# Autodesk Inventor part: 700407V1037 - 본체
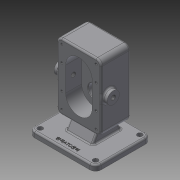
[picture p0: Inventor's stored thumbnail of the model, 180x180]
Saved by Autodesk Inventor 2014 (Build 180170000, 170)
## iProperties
Created: 2020-04
Part Number: 700407V1037 - 본체
Material: Generic
Document SubType Name: Modeling
Designer: kh
Density: 1 g/cm^3
Appearance: Default
Author: kh
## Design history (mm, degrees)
sketch "스케치1"
  geometry: L1 (-50, 60)-(50, 60); L2 (50, 60)-(50, -60); L3 (50, -60)-(-50, -60); L4 (-50, -60)-(-50, 60); L5 (-50, 60)-(50, -60); L6 (50, 60)-(-50, -60); 1 further point
  constraints: 12 end point, 2 midpoint, 2 parallel, 1 horizontal, 1 perpendicular
  dimensions: "d0" = 100 distance of L2.end L3.end; "d1" = 120 distance of L1.end L2.end
extrude "돌출1" new body sketch "스케치1" stored distance "d2" = 10; taper "d3" = 0 deg
node "작업 평면2"
  node "작업 평면1"
sketch "스케치2"
  geometry: L1 (-120, 0)-(-120, -10) reference; L2 (0, 0)-(-120, 0) reference; L3 (0, 0)-(0, -10) reference; L4 (-120, -10)-(0, -10) reference; L5 (-100, 140)-(-20, 140); L6 (-20, 140)-(-20, 20); L7 (-20, 20)-(-100, 20); L8 (-100, 20)-(-100, 140); L9 (-20, 80)-(-100, 80); L10 (-60, 20)-(-60, 80); 1 further point
  constraints: 12 end point, 4 midpoint, 2 parallel, 1 horizontal, 1 perpendicular, 1 point on line
  dimensions: "d5" = 80 distance of L5.start L5.end; "d6" = 150 distance between parallel lines of L5 L4; "d7" = 90 distance between parallel lines of L9 L4
extrude "돌출2" join sketch "스케치2" distance "d8" = 53; taper "d9" = 0 deg
fillet "모깎기1" dims "d10" = 9
sketch "스케치4"
  geometry: L1 (20, 29)-(20, 91) reference; L2 (131, 20)-(29, 20) reference; L3 (140, 91)-(140, 29) reference; L4 (29, 100)-(131, 100) reference; L5 (102, 60)-(58, 60); L6 (102, 84)-(58, 84); L7 (58, 36)-(102, 36); L8 (20, 29)-(20, 91) reference; L9 (80, 100)-(80, 20); C1 r 12.5 at (102, 60); C2 r 12.5 at (58, 60); C3 r 8.5 at (102, 60); C4 r 8.5 at (58, 60); A1 r 9 centre (29, 91) between (29, 100) and (20, 91) reference; A2 r 9 centre (29, 29) between (20, 29) and (29, 20) reference; A3 r 9 centre (131, 29) between (131, 20) and (140, 29) reference; A4 r 9 centre (131, 91) between (140, 91) and (131, 100) reference; A5 r 24 centre (102, 60) between (102, 36) and (102, 84); A6 r 24 centre (58, 60) between (58, 84) and (58, 36); 3 further points
  constraints: 10 end point, 6 centre point, 5 coincident, 4 midpoint, 4 point on circle, 4 tangent, 1 parallel, 1 perpendicular
  dimensions: "d11" = 44 distance of L5.end L5.start; "d12" = 24 radius of A5; "d13" = 25 diameter of C1; "d14" = 25 diameter of C2; "d15" = 17 diameter of C3; "d16" = 17 diameter of C4
  node "투영된 루프5"
extrude "돌출3" cut sketch "스케치4" distance "d17" = 29; taper "d18" = 0 deg
extrude "돌출4" cut sketch "스케치4" distance "d19" = 44; taper "d20" = 0 deg
extrude "돌출5" cut sketch "스케치4" distance "d21" = 44; taper "d22" = 0 deg
sketch "스케치5"
  geometry: L1 (-29, 100)-(-131, 100) reference; L2 (-140, 91)-(-140, 29) reference; L3 (-131, 20)-(-29, 20) reference; L4 (-20, 29)-(-20, 91) reference; C1 r 8.5 at (-102, 60) reference; C2 r 14 at (-102, 60); C3 r 8.5 at (-102, 60); A1 r 9 centre (-29, 91) between (-20, 91) and (-29, 100) reference; A2 r 9 centre (-131, 91) between (-131, 100) and (-140, 91) reference; A3 r 9 centre (-131, 29) between (-140, 29) and (-131, 20) reference; A4 r 9 centre (-29, 29) between (-29, 20) and (-20, 29) reference; 1 further point
  constraints: 2 centre point, 2 coincident
  dimensions: "d23" = 28 diameter of C2; "d24" = 17 diameter of C3
  node "투영된 루프6"
extrude "돌출7" cut sketch "스케치5" stored distance "d27" = 7.3; taper "d28" = 0 deg
node "작업 평면5"
  node "작업 평면4"
sketch "스케치6"
  geometry: C1 r 12.5 at (38, 0) reference; C2 r 19 at (38, 0); C3 r 14 at (38, 0); 1 further point
  constraints: 2 centre point, 2 coincident
  dimensions: "d30" = 38 diameter of C2; "d31" = 28 diameter of C3
extrude "돌출8" join sketch "스케치6" distance "d32" = 17; taper "d33" = 0 deg
extrude "돌출9" cut sketch "스케치4" stored distance "d34" = 7.3; taper "d35" = 0 deg
node "작업 평면7"
  node "작업 평면6"
sketch "스케치9"
  geometry: L1 (53, -102)-(0, -102) reference; L2 (53, 0)-(53, -102) reference; L3 (0, 0)-(53, 0) reference; L4 (0, 0)-(0, -102) reference; L5 (70, -141)-(-30, -141) reference; C1 r 11 at (14, -51); 1 further point
  constraints: 1 centre point
  dimensions: "d37" = 22 diameter of C1; "d38" = 90 distance from line of C1.centre L5; "d39" = 14 distance from line of L4 C1.centre
extrude "돌출10" join sketch "스케치9" stored distance "d40" = 7.3; taper "d41" = 0 deg
node "작업 평면8"
sketch "스케치10"
  geometry: L1 (44, 16.5)-(44, 41.5) reference; L2 (0, 102)-(53, 102) reference; L3 (0, 102)-(0, 0) reference; L4 (53, 0)-(0, 0) reference; L5 (53, 102)-(53, 0) reference; L6 (-30, 141)-(70, 141) reference; C1 r 11 at (14, 51); 1 further point
  constraints: 1 centre point
  dimensions: "d43" = 22 diameter of C1; "d44" = 90 distance from line of C1.centre L6; "d45" = 14 distance from line of L3 C1.centre
extrude "돌출11" join sketch "스케치10" stored distance "d46" = 7.3; taper "d47" = 0 deg
sketch "스케치11"
  geometry: C1 r 11 at (0, 0) reference; 2 further points
  constraints: 1 coincident
hole "구멍1" sketch "스케치11" at (0, 0) diameter "d48" = 8.376; stored, may be unused: countersink angle "d52" = 90 deg, drill point angle "d54" = 118 deg; dims "d49" = 6, "d50" = 4, "d51" = 2, "d53" = 8
sketch "스케치12"
  geometry: L1 (58, 84)-(102, 84) reference; L2 (102, 36)-(58, 36) reference; L3 (20, 29)-(20, 91) reference; L4 (131, 20)-(29, 20) reference; L5 (140, 91)-(140, 29) reference; L6 (29, 100)-(131, 100) reference; L7 (126, 60)-(34, 60); L8 (80, 84)-(80, 36); A1 r 24 centre (58, 60) between (58, 84) and (58, 36) reference; A2 r 24 centre (102, 60) between (102, 36) and (102, 84) reference; A3 r 9 centre (29, 91) between (29, 100) and (20, 91) reference; A4 r 9 centre (29, 29) between (20, 29) and (29, 20) reference; A5 r 9 centre (131, 29) between (131, 20) and (140, 29) reference; A6 r 9 centre (131, 91) between (140, 91) and (131, 100) reference; 9 further points
  constraints: 4 coincident, 4 end point, 2 midpoint, 2 point on circle, 2 symmetric about line
  dimensions: "d57" = 29 distance of point (29, 29) point (58, 29); "d58" = 29 distance of point (58, 91) point (29, 91); "d60" = 62 distance of point (58, 29) point (58, 91); "d64" = 44 distance of point (58, 29) point (102, 29)
hole "구멍2" sketch "스케치12" at (131, 91), (131, 29), (29, 29), (29, 91), (58, 29), (58, 91), (102, 29), (102, 91) diameter "d65" = 4.134; stored, may be unused: countersink angle "d69" = 90 deg, drill point angle "d71" = 118 deg; dims "d66" = 10, "d67" = 4, "d68" = 2, "d70" = 12
node "작업 평면9"
sketch "스케치13"
  geometry: L1 (100, -10)-(0, -10) reference; L2 (0, -10)-(0, 0) reference; L3 (0, 0)-(100, 0) reference; L4 (100, 0)-(100, -10) reference; L5 (83, 110.5)-(74, 110.5) reference; L6 (74, 110.5)-(74, 114.5) reference; L7 (74, 114.5)-(59, 114.5) reference; L8 (59, 114.5)-(59, 126) reference; L9 (59, 126)-(30, 126) reference; L10 (30, 126)-(30, 140) reference; L11 (30, 140)-(83, 140) reference; L12 (83, 140)-(83, 121) reference; L13 (83, 121)-(100, 121) reference; L14 (100, 121)-(100, 83) reference; L15 (74, 93.5)-(83, 93.5) reference; L16 (100, 83)-(83, 83) reference; L17 (83, 83)-(83, 20) reference; L18 (83, 20)-(30, 20) reference; L19 (30, 20)-(30, 34) reference; L20 (30, 34)-(59, 34) reference; L21 (59, 34)-(59, 45.5) reference; L22 (59, 45.5)-(74, 45.5) reference; L23 (74, 45.5)-(74, 70.5) reference; L24 (74, 70.5)-(59, 70.5) reference; L25 (59, 70.5)-(59, 89.5) reference; L26 (59, 89.5)-(74, 89.5) reference; L27 (74, 89.5)-(74, 93.5) reference; L28 (30, 0)-(41.547, 20); L29 (83, 0)-(71.453, 20); L30 (41.547, 20)-(71.453, 20); L31 (30, 0)-(83, 0); L32 (83, 93.5)-(83, 110.5) reference; 1 further point
  constraints: 8 end point, 4 point on line, 1 collinear, 1 parallel
  dimensions: "d72" = 17 distance from line of L4 L29.start; "d73" = 53 distance of L28.start L29.start; "d74" = 60 deg angle of L29 L3; "d75" = 60 deg angle of L28 L3
extrude "돌출12" join sketch "스케치13" stored distance "d76" = 48; taper "d77" = 0 deg
fillet "모깎기2" dims "d78" = 10
sketch "스케치14"
  geometry: L1 (50, 50)-(50, -50) reference; L2 (40, -60)-(-40, -60) reference; L3 (-50, -50)-(-50, 50) reference; L4 (-40, 60)-(40, 60) reference; A1 r 10 centre (40, 50) between (50, 50) and (40, 60) reference; A2 r 10 centre (40, -50) between (40, -60) and (50, -50) reference; A3 r 10 centre (-40, -50) between (-50, -50) and (-40, -60) reference; A4 r 10 centre (-40, 50) between (-40, 60) and (-50, 50) reference; 5 further points
  constraints: 4 coincident
hole "구멍3" sketch "스케치14" at (-40, 50), (40, 50), (40, -50), (-40, -50) diameter "d79" = 9; stored, may be unused: countersink angle "d83" = 90 deg, drill point angle "d85" = 0 deg; dims "d80" = 10, "d81" = 4, "d82" = 2, "d84" = 12
sketch "스케치16"
  geometry: C1 r 14 at (0, 0) reference; C2 r 19 at (0, 0) reference; C3 r 14 at (0, 0); 1 further point
  constraints: 1 centre point, 1 coincident
  dimensions: "d86" = 28 diameter of C3
extrude "돌출13" cut sketch "스케치16" distance "d87" = 7.3; taper "d88" = 0 deg
sketch "스케치17"
  geometry: C1 r 8.5 at (0, 0) reference; C2 r 8.5 at (0, 0); 1 further point
  constraints: 1 centre point, 1 coincident
  dimensions: "d89" = 17 diameter of C2
extrude "돌출14" cut sketch "스케치17" stored distance "d90" = 7.3; taper "d91" = 0 deg
fillet "모깎기3" dims "d92" = 0.5
chamfer "모따기1" distance "d93" = 0.7; stored, may be unused: second distance "d94" = 2, angle "d95" = 30 deg
fillet "모깎기5" dims "d97" = 3
fillet "모깎기6" dims "d98" = 3
fillet "모깎기7" dims "d99" = 3
fillet "모깎기8" dims "d100" = 3
fillet "모깎기9" dims "d101" = 3
fillet "모깎기10" dims "d102" = 3
fillet "모깎기11" dims "d103" = 3
sketch "스케치18"
  geometry: L1 (-59.22, 36.577)-(-59.22, -36.577); L2 (-59.22, -36.577)-(-20.78, -36.577); L3 (-20.78, -36.577)-(-20.78, 36.577); L4 (-20.78, 36.577)-(-59.22, 36.577); L5 (-40, -36.577)-(-40, 36.577); L6 (-20.78, 0)-(-59.22, 0); L7 (40, 60)-(-40, 60) reference; L8 (-50, 50)-(-50, -50) reference; 1 further point
  constraints: 4 end point, 4 midpoint, 2 other
  dimensions: "d104" = 60 distance between parallel lines of L7 L6; "d105" = 10 distance between parallel lines of L5 L8
feature "엠보싱1" sketch "스케치18" dims "d106" = 0.5, "d107" = 0
chamfer "모따기2" distance "d108" = 1; stored, may be unused: second distance "d109" = 2, angle "d110" = 30 deg
node "솔리드1"
node "투영된 루프1"
node "투영된 루프7"
node "투영된 루프8"
node "투영된 루프9"
node "투영된 루프10"
node "투영된 루프11"
node "투영된 루프12"
node "투영된 루프13"
node "절단 모서리 투영1"
other parameters: "d29" = 17, "d36" = 8, "d42" = 8
